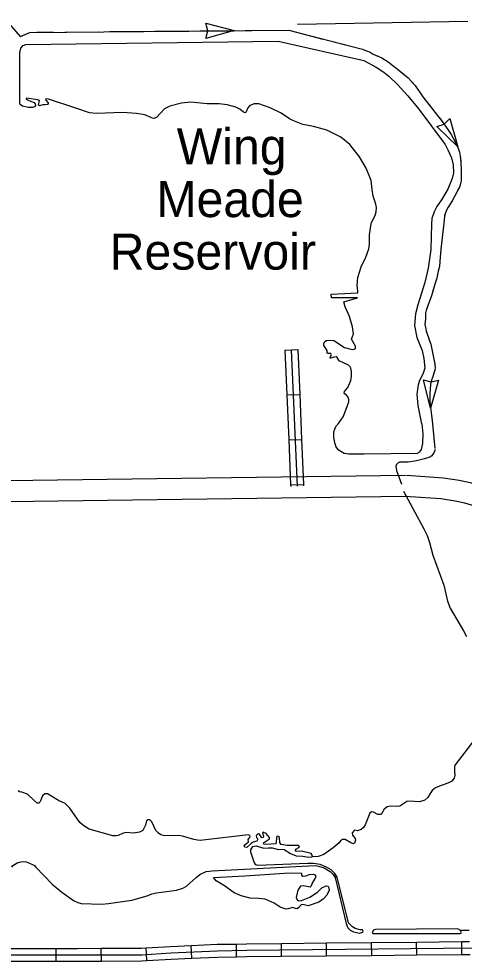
# Model space of a CAD drawing. Extents: x 982240 to 1103002, y 974866 to 1054902.
# Drawn here: x 1044274 to 1049490, y 991852 to 1002904 of the extents above; entities that cross this region are included whole.
import ezdxf

# ---------------------------------------------------------------- set-up
doc = ezdxf.new("R2010")
doc.units = 0
for name, color, linetype in [('10', 7, 'Continuous'), ('32', 7, 'Continuous'), ('35', 7, 'Continuous'), ('43', 7, 'Continuous'), ('5', 7, 'Continuous'), ('9', 7, 'Continuous')]:
    doc.layers.add(name, color=color, linetype=linetype)

msp = doc.modelspace()

# ---------------------------------------------------------------- linework, layer by layer
at = {"layer": '10'}
for points in [[(1044146, 997490), (1048804, 997551)], [(1048814, 997551), (1049247, 997522), (1049432, 997493), (1049560, 997467), (1049704, 997425), (1049760, 997400), (1049958, 997334), (1050180, 997286)], [(1048808, 997301), (1044149, 997240)], [(1050127, 997042), (1049892, 997092), (1049669, 997167), (1049617, 997190), (1049500, 997224), (1049387, 997247), (1049219, 997273), (1048798, 997302)]]:
    msp.add_lwpolyline(points, dxfattribs=at)
at = {"layer": '32'}
for p, q in [((1047392, 999020), (1047542, 999026)), ((1047414, 998493), (1047564, 998499)), ((1047436, 997965), (1047586, 997971)), ((1047458, 997438), (1047608, 997444)), ((1046824, 991903), (1046822, 992053)), ((1047352, 991909), (1047350, 992059)), ((1047880, 991915), (1047878, 992065)), ((1048408, 991920), (1048406, 992070)), ((1048936, 991926), (1048934, 992076)), ((1049462, 992081), (1049554, 992082)), ((1049464, 991931), (1049462, 992081)), ((1044712, 991852), (1044712, 992002)), ((1045241, 991853), (1045240, 992003)), ((1045773, 991858), (1045764, 992008)), ((1046299, 991886), (1046292, 992036)), ((1049464, 991931), (1049563, 991932))]:
    msp.add_line(p, q, dxfattribs=at)
for points in [[(1047392, 999020), (1047414, 998493)], [(1047466, 999023), (1047533, 997424)], [(1047542, 999026), (1047564, 998499)], [(1047414, 998493), (1047436, 997965)], [(1047564, 998499), (1047586, 997971)], [(1047436, 997965), (1047458, 997438)], [(1047586, 997971), (1047608, 997444)], [(1047458, 997438), (1047459, 997421)], [(1047608, 997444), (1047609, 997427)], [(1046292, 992036), (1046596, 992050), (1046822, 992053)], [(1046822, 992053), (1046942, 992055), (1047350, 992059)], [(1047350, 992059), (1047878, 992065)], [(1047878, 992065), (1048406, 992070)], [(1048406, 992070), (1048934, 992076)], [(1048934, 992076), (1049462, 992081)], [(1044184, 991926), (1044962, 991926), (1045714, 991928), (1046055, 991948), (1046598, 991974), (1046943, 991979), (1049633, 992007)], [(1044184, 992002), (1044712, 992002)], [(1044712, 992002), (1044962, 992002), (1045240, 992003)], [(1045240, 992003), (1045712, 992005), (1045764, 992008)], [(1045764, 992008), (1046051, 992024), (1046292, 992036)], [(1044184, 991852), (1044712, 991852)], [(1044712, 991852), (1044962, 991852), (1045241, 991853)], [(1045241, 991853), (1045716, 991855), (1045773, 991858)], [(1045773, 991858), (1046059, 991875), (1046299, 991886)], [(1046299, 991886), (1046600, 991900), (1046824, 991903)], [(1046824, 991903), (1046944, 991905), (1047352, 991909)], [(1047352, 991909), (1047880, 991915)], [(1047880, 991915), (1048408, 991920)], [(1048408, 991920), (1048936, 991926)], [(1048936, 991926), (1049464, 991931)]]:
    msp.add_lwpolyline(points, dxfattribs=at)
at = {"layer": '35'}
for points in [[(1044287, 1002509), (1044299, 1002562), (1044324, 1002591), (1044355, 1002602), (1047312, 1002643)], [(1047312, 1002643), (1048314, 1002415), (1048459, 1002337), (1048550, 1002279), (1048608, 1002232), (1048710, 1002136), (1048832, 1002003), (1048960, 1001846), (1049267, 1001430), (1049304, 1001362), (1049341, 1001276), (1049362, 1001192), (1049364, 1001100), (1049350, 1001031), (1049301, 1000906), (1049227, 1000783), (1049171, 1000703), (1049138, 1000642), (1049111, 1000561), (1049107, 1000495), (1049102, 1000199), (1049068, 999982), (1049032, 999811), (1048948, 999549), (1048921, 999443), (1048908, 999308), (1048936, 999168), (1048997, 999013), (1049020, 998919), (1049031, 998809), (1049007, 998736), (1048969, 998661), (1048953, 998613), (1048937, 998504), (1048948, 998371), (1048991, 998154)], [(1044592, 1001949), (1044617, 1001921), (1044619, 1001910), (1044608, 1001898), (1044579, 1001896), (1044555, 1001897), (1044529, 1001887), (1044516, 1001886), (1044504, 1001892), (1044515, 1001946), (1044492, 1001955), (1044366, 1001975), (1044359, 1001968), (1044360, 1001961), (1044392, 1001946), (1044454, 1001924), (1044464, 1001909), (1044468, 1001888), (1044457, 1001872), (1044434, 1001865), (1044383, 1001863), (1044318, 1001879), (1044291, 1001900), (1044284, 1001919), (1044287, 1002509)], [(1047935, 999631), (1047933, 999675), (1048244, 999689), (1048246, 999712), (1048238, 999781), (1048247, 999872), (1048286, 999995), (1048337, 1000109), (1048373, 1000208), (1048381, 1000259), (1048383, 1000371), (1048397, 1000478), (1048406, 1000517), (1048447, 1000598), (1048461, 1000642), (1048464, 1000692), (1048458, 1000730), (1048425, 1000823), (1048412, 1000902), (1048401, 1001010), (1048344, 1001151), (1048264, 1001285), (1048150, 1001432), (1048045, 1001517), (1047884, 1001600), (1047725, 1001641), (1047600, 1001666), (1047485, 1001711), (1047443, 1001733), (1047346, 1001797), (1047219, 1001862), (1047086, 1001907), (1047031, 1001908), (1046980, 1001887), (1046958, 1001860), (1046939, 1001813), (1046925, 1001802), (1046906, 1001808), (1046861, 1001844), (1046815, 1001868), (1046716, 1001897), (1046621, 1001907), (1046480, 1001909), (1046287, 1001927), (1046179, 1001917), (1046041, 1001880), (1045982, 1001849), (1045928, 1001796), (1045889, 1001751), (1045858, 1001737), (1045838, 1001740), (1045752, 1001777), (1045651, 1001795), (1045490, 1001804), (1045184, 1001793), (1045101, 1001800), (1044940, 1001858), (1044609, 1001965), (1044587, 1001961), (1044592, 1001949)], [(1048107, 998328), (1048138, 998413), (1048140, 998439), (1048131, 998468), (1048114, 998489), (1048087, 998511), (1048088, 998534), (1048127, 998580), (1048163, 998662), (1048170, 998713), (1048170, 998769), (1048164, 998806), (1048154, 998824), (1048134, 998841), (1048026, 998895), (1048004, 998933), (1047991, 998939), (1047964, 998938), (1047930, 998923), (1047923, 998926), (1047923, 998937), (1047935, 998963), (1047928, 998978), (1047896, 998978), (1047887, 998984), (1047887, 999013), (1047848, 999072), (1047846, 999091), (1047858, 999119), (1047879, 999130), (1047908, 999136), (1047963, 999133), (1048089, 999051), (1048180, 999026), (1048203, 999029), (1048216, 999039), (1048217, 999064), (1048170, 999148), (1048193, 999209), (1048184, 999291), (1048148, 999413), (1048096, 999525), (1048080, 999586), (1048242, 999634), (1047935, 999631)], [(1047984, 998121), (1048017, 998159), (1048073, 998235), (1048107, 998328)], [(1048140, 997804), (1048318, 997801), (1048943, 997811), (1048972, 997824), (1048990, 997855), (1049007, 997924), (1049010, 998036), (1048998, 998156)], [(1047984, 998121), (1047962, 998057), (1047962, 998003), (1047968, 997949), (1047986, 997884), (1048006, 997857), (1048086, 997812), (1048140, 997804)], [(1049146, 997853), (1049146, 997844), (1049138, 997822), (1049112, 997780), (1049087, 997762), (1049027, 997742), (1048932, 997719), (1048836, 997706)], [(1048836, 997706), (1048735, 997704), (1048717, 997695), (1048700, 997679), (1048692, 997656), (1048699, 997606), (1048757, 997447)], [(1048781, 997364), (1049020, 996923), (1049057, 996845), (1049086, 996764), (1049125, 996612), (1049254, 996261), (1049296, 996075), (1049326, 995991), (1049483, 995728), (1049519, 995660)], [(1049628, 994471), (1049385, 994154), (1049378, 994137), (1049379, 994071), (1049381, 994031), (1049375, 993999), (1049346, 993962), (1049300, 993940), (1049201, 993905), (1049154, 993884), (1049117, 993855), (1049091, 993818), (1049067, 993773), (1049031, 993739), (1048969, 993719), (1048849, 993730), (1048818, 993726), (1048736, 993671), (1048697, 993665), (1048625, 993669), (1048588, 993663), (1048555, 993634), (1048517, 993571), (1048481, 993571), (1048430, 993601), (1048405, 993602), (1048384, 993588), (1048332, 993450), (1048310, 993418), (1048283, 993395), (1048243, 993382), (1048207, 993388), (1048180, 993358), (1048182, 993328), (1048213, 993291), (1048218, 993273), (1048206, 993237), (1048194, 993230), (1048162, 993238), (1048095, 993279), (1048066, 993278), (1048042, 993264), (1048025, 993241), (1047958, 993181), (1047845, 993102), (1047781, 993078), (1047750, 993075), (1047715, 993081)], [(1046921, 992854), (1047388, 992883), (1047580, 992889), (1047586, 992879), (1047585, 992862), (1047602, 992847), (1047640, 992851), (1047675, 992870), (1047726, 992873), (1047745, 992865), (1047754, 992842), (1047747, 992825), (1047719, 992784), (1047694, 992729), (1047685, 992720), (1047628, 992730), (1047608, 992737), (1047574, 992732), (1047551, 992698), (1047539, 992670), (1047524, 992599), (1047533, 992572), (1047547, 992562), (1047560, 992559), (1047586, 992563), (1047683, 992604), (1047771, 992662), (1047823, 992712), (1047876, 992736), (1047893, 992731), (1047903, 992722), (1047908, 992685), (1047881, 992626), (1047842, 992582), (1047788, 992545), (1047665, 992500), (1047600, 992518), (1047582, 992512), (1047550, 992476), (1047532, 992467), (1047516, 992468), (1047480, 992481), (1047431, 992466), (1047404, 992463), (1047335, 992485), (1047264, 992532), (1047159, 992581), (1047082, 992587), (1046985, 992590), (1046879, 992617), (1046798, 992654), (1046683, 992737), (1046584, 992796), (1046556, 992835)], [(1046556, 992835), (1046921, 992854)], [(1049414, 992233), (1048454, 992222), (1048427, 992215), (1048412, 992190), (1048422, 992178), (1049445, 992177)], [(1049457, 992191), (1049449, 992207), (1049434, 992223), (1049414, 992233)], [(1049445, 992177), (1049460, 992185), (1049457, 992191)], [(1049551, 992213), (1049446, 992213)]]:
    msp.add_lwpolyline(points, dxfattribs=at)
at = {"layer": '43'}
for p, q in [((1046488, 1002764), (1046463, 1002852)), ((1046463, 1002852), (1046795, 1002766)), ((1046795, 1002766), (1046465, 1002674)), ((1046465, 1002674), (1046488, 1002763)), ((1046488, 1002763), (1046488, 1002764)), ((1049258, 1001669), (1049322, 1001734)), ((1049322, 1001734), (1049415, 1001404)), ((1049169, 1001643), (1049257, 1001668)), ((1049415, 1001404), (1049169, 1001643)), ((1049257, 1001668), (1049258, 1001669)), ((1049097, 998338), (1049014, 998671)), ((1049014, 998671), (1049102, 998645)), ((1049192, 998667), (1049097, 998338)), ((1049102, 998645), (1049103, 998645)), ((1049103, 998645), (1049192, 998667))]:
    msp.add_line(p, q, dxfattribs=at)
for points in [[(1044110, 1002904), (1044291, 1002698)], [(1044291, 1002698), (1044401, 1002746), (1047435, 1002771)], [(1044295, 1002699), (1044401, 1002746), (1044483, 1002747)], [(1044483, 1002747), (1044681, 1002749)], [(1044813, 1002750), (1045209, 1002753)], [(1045341, 1002754), (1045737, 1002757)], [(1045869, 1002758), (1046265, 1002761)], [(1046397, 1002762), (1046793, 1002765)], [(1046925, 1002766), (1047321, 1002770)], [(1047435, 1002771), (1048298, 1002547), (1048347, 1002531), (1048389, 1002512), (1048425, 1002492), (1048526, 1002447), (1048599, 1002399), (1048654, 1002359), (1048705, 1002317), (1048833, 1002214), (1048917, 1002121), (1049008, 1001991)], [(1047452, 1002766), (1047644, 1002717)], [(1047644, 1002717), (1047835, 1002667)], [(1047963, 1002634), (1048298, 1002547), (1048345, 1002531)], [(1048465, 1002475), (1048526, 1002447), (1048599, 1002399), (1048654, 1002359), (1048705, 1002317), (1048788, 1002250)], [(1048883, 1002158), (1048917, 1002121), (1049008, 1001991), (1049123, 1001843)], [(1049008, 1001991), (1049235, 1001699), (1049299, 1001608), (1049340, 1001546), (1049387, 1001460), (1049410, 1001412), (1049425, 1001377), (1049438, 1001339), (1049445, 1001292), (1049452, 1001223), (1049456, 1001127), (1049457, 1001038), (1049456, 1001008), (1049451, 1000984), (1049445, 1000958), (1049435, 1000932), (1049352, 1000768), (1049302, 1000694), (1049283, 1000660), (1049267, 1000618), (1049260, 1000587), (1049255, 1000548), (1049252, 1000508), (1049217, 1000203), (1049207, 1000060), (1049200, 999999), (1049188, 999943), (1049180, 999905), (1049172, 999861), (1049152, 999803), (1049108, 999654), (1049056, 999519), (1049045, 999483), (1049039, 999454), (1049038, 999426), (1049038, 999385), (1049032, 999319), (1049037, 999285), (1049049, 999229), (1049068, 999178), (1049086, 999126), (1049100, 999088), (1049114, 999030), (1049144, 998874), (1049150, 998815), (1049148, 998783), (1049137, 998750), (1049124, 998710), (1049104, 998653), (1049096, 998618), (1049088, 998505), (1049089, 998407), (1049115, 998193), (1049146, 997866)], [(1049204, 1001739), (1049235, 1001699), (1049299, 1001608), (1049340, 1001546), (1049387, 1001460), (1049410, 1001412), (1049413, 1001404)], [(1049446, 1001278), (1049452, 1001223), (1049456, 1001127), (1049457, 1001038), (1049456, 1001008), (1049451, 1000984), (1049445, 1000958), (1049435, 1000932), (1049414, 1000890)], [(1049354, 1000772), (1049352, 1000768), (1049302, 1000694), (1049283, 1000660), (1049267, 1000618), (1049262, 1000599)], [(1049262, 1000599), (1049260, 1000587), (1049255, 1000548), (1049252, 1000508), (1049240, 1000402)], [(1049225, 1000271), (1049217, 1000203), (1049207, 1000060), (1049200, 999999), (1049188, 999943), (1049180, 999905), (1049175, 999879)], [(1049137, 999752), (1049108, 999654), (1049056, 999519), (1049045, 999483), (1049039, 999454), (1049038, 999426), (1049038, 999385), (1049037, 999373)], [(1049046, 999242), (1049049, 999229), (1049068, 999178), (1049086, 999126), (1049100, 999088), (1049114, 999030), (1049144, 998874), (1049146, 998860)], [(1049131, 998731), (1049124, 998710), (1049104, 998653), (1049096, 998618), (1049088, 998505), (1049089, 998407), (1049097, 998341)], [(1049113, 998210), (1049115, 998193), (1049142, 997905)]]:
    msp.add_lwpolyline(points, dxfattribs=at)
at = {"layer": '5'}
msp.add_lwpolyline([(1047537, 1002843), (1049532, 1002879)], dxfattribs=at)
at = {"layer": '9'}
for points in [[(1044453, 993736), (1044377, 993810), (1044310, 993833), (1044282, 993839), (1044268, 993848)], [(1046366, 993270), (1046323, 993278), (1046193, 993318), (1046147, 993327), (1045983, 993321), (1045939, 993335), (1045910, 993354), (1045878, 993386), (1045834, 993488), (1045808, 993510), (1045785, 993509), (1045771, 993498), (1045756, 993446), (1045726, 993385), (1045689, 993363), (1045617, 993352), (1045529, 993360), (1045487, 993351), (1045438, 993326), (1045414, 993321), (1045375, 993322), (1045098, 993402), (1045036, 993440), (1044987, 993480), (1044873, 993645), (1044815, 993700), (1044738, 993736), (1044608, 993816), (1044577, 993814), (1044553, 993790), (1044529, 993731), (1044521, 993715), (1044507, 993705), (1044487, 993707), (1044453, 993736)], [(1047715, 993081), (1047707, 993104), (1047700, 993113), (1047587, 993144), (1047524, 993138), (1047513, 993148), (1047526, 993169), (1047556, 993184), (1047560, 993198), (1047551, 993207), (1047533, 993210), (1047416, 993207), (1047349, 993222), (1047333, 993243), (1047327, 993297), (1047322, 993311), (1047309, 993318), (1047298, 993315), (1047292, 993305), (1047287, 993235), (1047279, 993227), (1047170, 993219), (1047145, 993224), (1047142, 993240), (1047209, 993288), (1047210, 993304), (1047173, 993348), (1047136, 993364), (1047128, 993357), (1047140, 993317), (1047138, 993303), (1047120, 993300), (1047098, 993333), (1047082, 993346), (1047070, 993341), (1047056, 993324), (1047060, 993304), (1047070, 993289), (1047071, 993276), (1047063, 993260), (1047019, 993246), (1046997, 993232), (1046945, 993186), (1046921, 993189), (1046915, 993205), (1046923, 993216), (1046964, 993252), (1046962, 993278), (1046980, 993302), (1046983, 993318), (1046974, 993329), (1046963, 993333), (1046430, 993271), (1046405, 993267), (1046366, 993270)], [(1047658, 992997), (1047073, 992974), (1047050, 992981), (1047029, 993014), (1046992, 993129), (1046993, 993159), (1047016, 993197), (1047054, 993204), (1047146, 993177), (1047197, 993181), (1047241, 993180), (1047314, 993160), (1047352, 993165), (1047382, 993160), (1047458, 993114), (1047524, 993089), (1047599, 993085), (1047667, 993073), (1047706, 993074), (1047715, 993081)], [(1044193, 992955), (1044205, 992973), (1044261, 993010), (1044318, 993020), (1044360, 993017), (1044393, 993007), (1044456, 992975), (1044474, 992956)], [(1044474, 992956), (1044664, 992756), (1044777, 992663), (1044916, 992564), (1044967, 992541), (1045005, 992530), (1045243, 992521), (1045323, 992529), (1045597, 992569), (1045777, 992620), (1045832, 992641), (1045885, 992653), (1046122, 992686), (1046194, 992707), (1046239, 992732), (1046350, 992835), (1046396, 992870), (1046468, 992905), (1046538, 992913), (1047747, 992974), (1047784, 992968), (1047851, 992945), (1047920, 992903), (1047958, 992869), (1047980, 992833)], [(1048002, 992837), (1047976, 992881), (1047934, 992925), (1047879, 992955), (1047805, 992986), (1047726, 992996), (1047658, 992997)], [(1047980, 992833), (1048108, 992294), (1048129, 992243), (1048156, 992217), (1048193, 992194), (1048265, 992182), (1048304, 992192), (1048309, 992204), (1048298, 992220), (1048273, 992220), (1048213, 992234), (1048183, 992256), (1048135, 992301), (1048002, 992837)]]:
    msp.add_lwpolyline(points, dxfattribs=at)

# ---------------------------------------------------------------- texts
at = {"layer": '35'}
for s, p in [('Wing', (1046124, 1001196)), ('Meade', (1045885, 1000579)), ('Reservoir', (1045338, 999963))]:
    msp.add_text(s, height=422.4, dxfattribs=at).set_placement(p)

doc.saveas('drawing.dxf')
